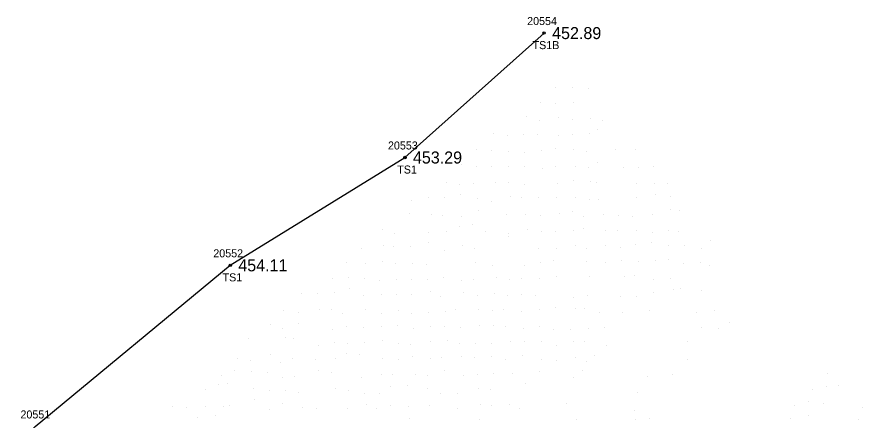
# Model space of a CAD drawing. Extents: x 1747760 to 1751131, y 649333 to 653784.
# Drawn here: x 1749099.9 to 1749205.4, y 651497.2 to 651547.5 of the extents above; entities that cross this region are included whole.
import ezdxf

# ---------------------------------------------------------------- set-up
doc = ezdxf.new("R2010")
doc.units = 0
for name, color, linetype in [('RD_DTM_BkLn2', 7, 'Continuous'), ('RD_DTM_BkLn_txCode', 7, 'Continuous'), ('RD_DTM_Spot', 7, 'Continuous'), ('RD_EX_TX_Misc_ELEV', 7, 'Continuous'), ('RD_SMD_Locator', 7, 'Continuous')]:
    doc.layers.add(name, color=color, linetype=linetype)

msp = doc.modelspace()

# ---------------------------------------------------------------- linework, layer by layer
at = {"layer": 'RD_DTM_BkLn2'}
msp.add_lwpolyline([(1749072.45, 651463.57), (1749102.17, 651496.37), (1749126.54, 651516.47), (1749148.35, 651529.92), (1749165.73, 651545.44)], dxfattribs=at)
at = {"layer": 'RD_DTM_Spot'}
for p, q in [((1749167.21, 651538.67), (1749167.21, 651538.67)), ((1749169.28, 651538.7), (1749169.28, 651538.7)), ((1749171.29, 651538.5), (1749171.29, 651538.5)), ((1749165.3, 651536.76), (1749165.3, 651536.76)), ((1749167.21, 651536.69), (1749167.21, 651536.69)), ((1749169.37, 651536.81), (1749169.37, 651536.81)), ((1749163.47, 651534.99), (1749163.47, 651534.99)), ((1749165.16, 651534.49), (1749165.16, 651534.49)), ((1749167.54, 651534.9), (1749167.54, 651534.9)), ((1749169.24, 651534.7), (1749169.24, 651534.7)), ((1749171.49, 651534.78), (1749171.49, 651534.78)), ((1749173, 651534.52), (1749173, 651534.52)), ((1749172.43, 651533.45), (1749172.43, 651533.45)), ((1749159.35, 651532.94), (1749159.35, 651532.94)), ((1749161.13, 651532.71), (1749161.13, 651532.71)), ((1749163.13, 651532.76), (1749163.13, 651532.76)), ((1749164.86, 651532.77), (1749164.86, 651532.77)), ((1749167.54, 651532.69), (1749167.54, 651532.69)), ((1749169.27, 651532.75), (1749169.27, 651532.75)), ((1749171.39, 651532.86), (1749171.39, 651532.86)), ((1749167.17, 651531.08), (1749167.17, 651531.08)), ((1749169.37, 651530.98), (1749169.37, 651530.98)), ((1749157.32, 651530.86), (1749157.32, 651530.86)), ((1749159.19, 651530.83), (1749159.19, 651530.83)), ((1749161.3, 651530.69), (1749161.3, 651530.69)), ((1749163.22, 651530.58), (1749163.22, 651530.58)), ((1749165.42, 651530.85), (1749165.42, 651530.85)), ((1749171.01, 651530.7), (1749171.01, 651530.7)), ((1749174.69, 651530.92), (1749174.69, 651530.92)), ((1749177.18, 651530.96), (1749177.18, 651530.96)), ((1749155.41, 651529.01), (1749155.41, 651529.01)), ((1749172.35, 651529.27), (1749172.35, 651529.27)), ((1749157.31, 651528.79), (1749157.31, 651528.79)), ((1749159.22, 651528.74), (1749159.22, 651528.74)), ((1749161.32, 651528.76), (1749161.32, 651528.76)), ((1749163.27, 651528.78), (1749163.27, 651528.78)), ((1749165.47, 651528.58), (1749165.47, 651528.58)), ((1749167.14, 651528.79), (1749167.14, 651528.79)), ((1749169.6, 651528.85), (1749169.6, 651528.85)), ((1749171.25, 651528.63), (1749171.25, 651528.63)), ((1749175.66, 651528.64), (1749175.66, 651528.64)), ((1749177.55, 651528.71), (1749177.55, 651528.71)), ((1749179.34, 651528.84), (1749179.34, 651528.84)), ((1749153.57, 651526.76), (1749153.57, 651526.76)), ((1749159.6, 651526.86), (1749159.6, 651526.86)), ((1749161.32, 651526.77), (1749161.32, 651526.77)), ((1749169.42, 651527.04), (1749169.42, 651527.04)), ((1749171.49, 651526.91), (1749171.49, 651526.91)), ((1749172.28, 651526.85), (1749172.28, 651526.85)), ((1749155.17, 651526.59), (1749155.17, 651526.59)), ((1749156.89, 651526.73), (1749156.89, 651526.73)), ((1749163.34, 651526.58), (1749163.34, 651526.58)), ((1749167.41, 651526.7), (1749167.41, 651526.7)), ((1749177.32, 651526.64), (1749177.32, 651526.64)), ((1749179.5, 651526.71), (1749179.5, 651526.71)), ((1749181.14, 651526.71), (1749181.14, 651526.71)), ((1749151.31, 651524.97), (1749151.31, 651524.97)), ((1749153.31, 651524.92), (1749153.31, 651524.92)), ((1749155.28, 651525.25), (1749155.28, 651525.25)), ((1749157.4, 651524.86), (1749157.4, 651524.86)), ((1749161.53, 651525), (1749161.53, 651525)), ((1749162.89, 651524.91), (1749162.89, 651524.91)), ((1749165.01, 651524.92), (1749165.01, 651524.92)), ((1749167.32, 651524.94), (1749167.32, 651524.94)), ((1749169.67, 651524.93), (1749169.67, 651524.93)), ((1749171.39, 651524.66), (1749171.39, 651524.66)), ((1749172.58, 651524.71), (1749172.58, 651524.71)), ((1749177.27, 651524.98), (1749177.27, 651524.98)), ((1749179.66, 651525.26), (1749179.66, 651525.26)), ((1749181.56, 651525), (1749181.56, 651525)), ((1749149.14, 651524.6), (1749149.14, 651524.6)), ((1749159.21, 651524.47), (1749159.21, 651524.47)), ((1749148.87, 651522.98), (1749148.87, 651522.98)), ((1749151.67, 651522.85), (1749151.67, 651522.85)), ((1749153.08, 651522.65), (1749153.08, 651522.65)), ((1749155.37, 651522.62), (1749155.37, 651522.62)), ((1749157.51, 651523.29), (1749157.51, 651523.29)), ((1749161.08, 651522.81), (1749161.08, 651522.81)), ((1749163.46, 651522.78), (1749163.46, 651522.78)), ((1749165.3, 651522.7), (1749165.3, 651522.7)), ((1749167.65, 651522.98), (1749167.65, 651522.98)), ((1749169.31, 651523.2), (1749169.31, 651523.2)), ((1749170.67, 651522.53), (1749170.67, 651522.53)), ((1749173.11, 651522.85), (1749173.11, 651522.85)), ((1749175.05, 651522.63), (1749175.05, 651522.63)), ((1749176.79, 651522.58), (1749176.79, 651522.58)), ((1749179.28, 651522.85), (1749179.28, 651522.85)), ((1749181.57, 651523.41), (1749181.57, 651523.41)), ((1749182.58, 651523.37), (1749182.58, 651523.37)), ((1749156.84, 651521.55), (1749156.84, 651521.55)), ((1749145.55, 651520.88), (1749145.55, 651520.88)), ((1749147.04, 651520.48), (1749147.04, 651520.48)), ((1749151.29, 651520.56), (1749151.29, 651520.56)), ((1749153.49, 651520.75), (1749153.49, 651520.75)), ((1749155.18, 651521.34), (1749155.18, 651521.34)), ((1749158.41, 651520.66), (1749158.41, 651520.66)), ((1749161.22, 651520.48), (1749161.22, 651520.48)), ((1749163.69, 651520.95), (1749163.69, 651520.95)), ((1749165.35, 651520.7), (1749165.35, 651520.7)), ((1749167.14, 651520.67), (1749167.14, 651520.67)), ((1749169.34, 651520.76), (1749169.34, 651520.76)), ((1749170.62, 651521.04), (1749170.62, 651521.04)), ((1749173.36, 651520.79), (1749173.36, 651520.79)), ((1749174.86, 651520.82), (1749174.86, 651520.82)), ((1749177.27, 651520.86), (1749177.27, 651520.86)), ((1749179.32, 651520.55), (1749179.32, 651520.55)), ((1749181.27, 651520.85), (1749181.27, 651520.85)), ((1749182.51, 651520.68), (1749182.51, 651520.68)), ((1749161.25, 651520.06), (1749161.25, 651520.06)), ((1749186.45, 651519.55), (1749186.45, 651519.55)), ((1749142.97, 651518.58), (1749142.97, 651518.58)), ((1749145.63, 651518.96), (1749145.63, 651518.96)), ((1749146.86, 651518.88), (1749146.86, 651518.88)), ((1749149.06, 651518.76), (1749149.06, 651518.76)), ((1749151.32, 651519.29), (1749151.32, 651519.29)), ((1749155.48, 651518.97), (1749155.48, 651518.97)), ((1749157.04, 651518.59), (1749157.04, 651518.59)), ((1749164.98, 651518.63), (1749164.98, 651518.63)), ((1749167.22, 651518.56), (1749167.22, 651518.56)), ((1749169.63, 651518.96), (1749169.63, 651518.96)), ((1749171.05, 651518.6), (1749171.05, 651518.6)), ((1749173.38, 651518.99), (1749173.38, 651518.99)), ((1749175.23, 651518.7), (1749175.23, 651518.7)), ((1749177.12, 651519.1), (1749177.12, 651519.1)), ((1749179.14, 651519.27), (1749179.14, 651519.27)), ((1749181.22, 651518.98), (1749181.22, 651518.98)), ((1749183.2, 651518.89), (1749183.2, 651518.89)), ((1749185.43, 651518.53), (1749185.43, 651518.53)), ((1749153.3, 651518.3), (1749153.3, 651518.3)), ((1749141.11, 651516.79), (1749141.11, 651516.79)), ((1749143.38, 651516.76), (1749143.38, 651516.76)), ((1749145.6, 651516.96), (1749145.6, 651516.96)), ((1749147.23, 651516.76), (1749147.23, 651516.76)), ((1749149.34, 651516.64), (1749149.34, 651516.64)), ((1749151.05, 651516.57), (1749151.05, 651516.57)), ((1749157.19, 651516.87), (1749157.19, 651516.87)), ((1749159.27, 651516.44), (1749159.27, 651516.44)), ((1749163.29, 651516.51), (1749163.29, 651516.51)), ((1749165.33, 651516.88), (1749165.33, 651516.88)), ((1749166.93, 651517.04), (1749166.93, 651517.04)), ((1749171.02, 651517), (1749171.02, 651517)), ((1749173.41, 651516.84), (1749173.41, 651516.84)), ((1749175.45, 651517.11), (1749175.45, 651517.11)), ((1749177.57, 651516.95), (1749177.57, 651516.95)), ((1749179.66, 651517.06), (1749179.66, 651517.06)), ((1749181.25, 651517.24), (1749181.25, 651517.24)), ((1749183.11, 651516.64), (1749183.11, 651516.64)), ((1749185.26, 651516.87), (1749185.26, 651516.87)), ((1749186.44, 651516.51), (1749186.44, 651516.51)), ((1749177.02, 651515.25), (1749177.02, 651515.25)), ((1749139.35, 651514.86), (1749139.35, 651514.86)), ((1749141.29, 651514.98), (1749141.29, 651514.98)), ((1749143.25, 651514.77), (1749143.25, 651514.77)), ((1749145.2, 651514.58), (1749145.2, 651514.58)), ((1749147.35, 651514.71), (1749147.35, 651514.71)), ((1749149.19, 651514.75), (1749149.19, 651514.75)), ((1749151.15, 651514.69), (1749151.15, 651514.69)), ((1749153.19, 651514.94), (1749153.19, 651514.94)), ((1749155.38, 651514.58), (1749155.38, 651514.58)), ((1749156.93, 651514.68), (1749156.93, 651514.68)), ((1749159.73, 651515), (1749159.73, 651515)), ((1749161.4, 651514.71), (1749161.4, 651514.71)), ((1749162.92, 651514.82), (1749162.92, 651514.82)), ((1749165.17, 651514.84), (1749165.17, 651514.84)), ((1749167.28, 651515.06), (1749167.28, 651515.06)), ((1749171.45, 651515.04), (1749171.45, 651515.04)), ((1749175.8, 651515.05), (1749175.8, 651515.05)), ((1749179.36, 651514.74), (1749179.36, 651514.74)), ((1749181.57, 651514.87), (1749181.57, 651514.87)), ((1749139.56, 651513.04), (1749139.56, 651513.04)), ((1749141.48, 651513.52), (1749141.48, 651513.52)), ((1749151.52, 651513.21), (1749151.52, 651513.21)), ((1749155.69, 651513.05), (1749155.69, 651513.05)), ((1749179.4, 651513.05), (1749179.4, 651513.05)), ((1749181.88, 651513.5), (1749181.88, 651513.5)), ((1749182.76, 651513.64), (1749182.76, 651513.64)), ((1749185.38, 651513.38), (1749185.38, 651513.38)), ((1749135.49, 651512.98), (1749135.49, 651512.98)), ((1749137.37, 651512.91), (1749137.37, 651512.91)), ((1749143.19, 651512.68), (1749143.19, 651512.68)), ((1749145.4, 651512.83), (1749145.4, 651512.83)), ((1749147.34, 651512.89), (1749147.34, 651512.89)), ((1749149.15, 651512.83), (1749149.15, 651512.83)), ((1749152.85, 651512.63), (1749152.85, 651512.63)), ((1749157.47, 651512.75), (1749157.47, 651512.75)), ((1749159.54, 651512.94), (1749159.54, 651512.94)), ((1749161.13, 651512.75), (1749161.13, 651512.75)), ((1749162.96, 651512.88), (1749162.96, 651512.88)), ((1749164.61, 651512.7), (1749164.61, 651512.7)), ((1749169.39, 651512.48), (1749169.39, 651512.48)), ((1749171.18, 651512.74), (1749171.18, 651512.74)), ((1749175.28, 651512.63), (1749175.28, 651512.63)), ((1749177.31, 651512.53), (1749177.31, 651512.53)), ((1749137.62, 651510.98), (1749137.62, 651510.98)), ((1749143.37, 651510.95), (1749143.37, 651510.95)), ((1749154.69, 651511.02), (1749154.69, 651511.02)), ((1749157.56, 651510.92), (1749157.56, 651510.92)), ((1749160.66, 651510.99), (1749160.66, 651510.99)), ((1749167.15, 651511.15), (1749167.15, 651511.15)), ((1749169.59, 651511.03), (1749169.59, 651511.03)), ((1749170.83, 651511.03), (1749170.83, 651511.03)), ((1749133.13, 651510.8), (1749133.13, 651510.8)), ((1749135.09, 651510.53), (1749135.09, 651510.53)), ((1749139.24, 651510.9), (1749139.24, 651510.9)), ((1749140.52, 651510.41), (1749140.52, 651510.41)), ((1749145.38, 651510.49), (1749145.38, 651510.49)), ((1749147.6, 651510.89), (1749147.6, 651510.89)), ((1749149.12, 651510.46), (1749149.12, 651510.46)), ((1749151.32, 651510.58), (1749151.32, 651510.58)), ((1749153.37, 651510.76), (1749153.37, 651510.76)), ((1749159.27, 651510.85), (1749159.27, 651510.85)), ((1749162.93, 651510.66), (1749162.93, 651510.66)), ((1749165.17, 651510.92), (1749165.17, 651510.92)), ((1749172.6, 651510.63), (1749172.6, 651510.63)), ((1749175.47, 651510.58), (1749175.47, 651510.58)), ((1749178.93, 651510.8), (1749178.93, 651510.8)), ((1749184.8, 651510.6), (1749184.8, 651510.6)), ((1749187, 651510.87), (1749187, 651510.87)), ((1749131.52, 651509.09), (1749131.52, 651509.09)), ((1749135.06, 651509.18), (1749135.06, 651509.18)), ((1749145.45, 651508.86), (1749145.45, 651508.86)), ((1749147.37, 651508.93), (1749147.37, 651508.93)), ((1749153.23, 651508.87), (1749153.23, 651508.87)), ((1749157.62, 651508.98), (1749157.62, 651508.98)), ((1749159.36, 651509), (1749159.36, 651509)), ((1749165.18, 651508.81), (1749165.18, 651508.81)), ((1749188.87, 651509.3), (1749188.87, 651509.3)), ((1749133.07, 651508.56), (1749133.07, 651508.56)), ((1749139.34, 651508.41), (1749139.34, 651508.41)), ((1749141.03, 651508.78), (1749141.03, 651508.78)), ((1749143.23, 651508.71), (1749143.23, 651508.71)), ((1749149.47, 651508.65), (1749149.47, 651508.65)), ((1749151.5, 651508.79), (1749151.5, 651508.79)), ((1749155.32, 651508.72), (1749155.32, 651508.72)), ((1749160.91, 651508.78), (1749160.91, 651508.78)), ((1749163.2, 651508.6), (1749163.2, 651508.6)), ((1749166.9, 651508.52), (1749166.9, 651508.52)), ((1749168.98, 651508.45), (1749168.98, 651508.45)), ((1749171.31, 651508.55), (1749171.31, 651508.55)), ((1749173.29, 651508.72), (1749173.29, 651508.72)), ((1749185.38, 651508.66), (1749185.38, 651508.66)), ((1749187.47, 651508.55), (1749187.47, 651508.55)), ((1749128.8, 651507.33), (1749128.8, 651507.33)), ((1749133.42, 651507.41), (1749133.42, 651507.41)), ((1749134.45, 651507.39), (1749134.45, 651507.39)), ((1749139.61, 651506.82), (1749139.61, 651506.82)), ((1749143.27, 651506.83), (1749143.27, 651506.83)), ((1749145.55, 651507.04), (1749145.55, 651507.04)), ((1749151.49, 651507.03), (1749151.49, 651507.03)), ((1749153.63, 651507.1), (1749153.63, 651507.1)), ((1749157.2, 651506.77), (1749157.2, 651506.77)), ((1749159.18, 651506.73), (1749159.18, 651506.73)), ((1749161.54, 651507.02), (1749161.54, 651507.02)), ((1749163.31, 651506.91), (1749163.31, 651506.91)), ((1749165.46, 651506.99), (1749165.46, 651506.99)), ((1749169.41, 651507.02), (1749169.41, 651507.02)), ((1749170.76, 651507.01), (1749170.76, 651507.01)), ((1749183.65, 651507), (1749183.65, 651507)), ((1749137.53, 651506.52), (1749137.53, 651506.52)), ((1749141.14, 651506.67), (1749141.14, 651506.67)), ((1749147.51, 651506.68), (1749147.51, 651506.68)), ((1749149.1, 651506.61), (1749149.1, 651506.61)), ((1749155.13, 651506.66), (1749155.13, 651506.66)), ((1749167.33, 651506.47), (1749167.33, 651506.47)), ((1749173.47, 651506.44), (1749173.47, 651506.44)), ((1749127.48, 651504.91), (1749127.48, 651504.91)), ((1749129.01, 651504.59), (1749129.01, 651504.59)), ((1749131.6, 651505.36), (1749131.6, 651505.36)), ((1749134.26, 651504.84), (1749134.26, 651504.84)), ((1749137.21, 651504.78), (1749137.21, 651504.78)), ((1749139.71, 651504.8), (1749139.71, 651504.8)), ((1749141.06, 651505.49), (1749141.06, 651505.49)), ((1749142.67, 651505.36), (1749142.67, 651505.36)), ((1749145.5, 651504.86), (1749145.5, 651504.86)), ((1749147.54, 651504.68), (1749147.54, 651504.68)), ((1749149.35, 651505.14), (1749149.35, 651505.14)), ((1749151.5, 651504.87), (1749151.5, 651504.87)), ((1749152.87, 651504.96), (1749152.87, 651504.96)), ((1749155.41, 651505.05), (1749155.41, 651505.05)), ((1749157.04, 651504.96), (1749157.04, 651504.96)), ((1749159.11, 651505.08), (1749159.11, 651505.08)), ((1749160.94, 651504.78), (1749160.94, 651504.78)), ((1749163.01, 651505.22), (1749163.01, 651505.22)), ((1749165.38, 651504.72), (1749165.38, 651504.72)), ((1749167.3, 651504.66), (1749167.3, 651504.66)), ((1749169.69, 651504.97), (1749169.69, 651504.97)), ((1749172.01, 651505.25), (1749172.01, 651505.25)), ((1749183.58, 651504.71), (1749183.58, 651504.71)), ((1749132.76, 651504.34), (1749132.76, 651504.34)), ((1749170.96, 651504.43), (1749170.96, 651504.43)), ((1749125.41, 651502.76), (1749125.41, 651502.76)), ((1749127.08, 651503.4), (1749127.08, 651503.4)), ((1749129.18, 651503.25), (1749129.18, 651503.25)), ((1749131.13, 651503.05), (1749131.13, 651503.05)), ((1749134.54, 651502.65), (1749134.54, 651502.65)), ((1749137.55, 651503.36), (1749137.55, 651503.36)), ((1749139.18, 651503.1), (1749139.18, 651503.1)), ((1749142.97, 651502.49), (1749142.97, 651502.49)), ((1749145.46, 651502.81), (1749145.46, 651502.81)), ((1749146.83, 651502.89), (1749146.83, 651502.89)), ((1749149.68, 651502.85), (1749149.68, 651502.85)), ((1749151.15, 651502.73), (1749151.15, 651502.73)), ((1749153.34, 651503.36), (1749153.34, 651503.36)), ((1749155.64, 651502.75), (1749155.64, 651502.75)), ((1749157.39, 651502.84), (1749157.39, 651502.84)), ((1749159.42, 651502.98), (1749159.42, 651502.98)), ((1749161.78, 651502.97), (1749161.78, 651502.97)), ((1749165.17, 651503.2), (1749165.17, 651503.2)), ((1749169.35, 651502.47), (1749169.35, 651502.47)), ((1749170.5, 651503.41), (1749170.5, 651503.41)), ((1749178.65, 651502.66), (1749178.65, 651502.66)), ((1749181.71, 651502.91), (1749181.71, 651502.91)), ((1749201.11, 651502.95), (1749201.11, 651502.95)), ((1749125.01, 651501.59), (1749125.01, 651501.59)), ((1749126.24, 651501.73), (1749126.24, 651501.73)), ((1749133.04, 651502.43), (1749133.04, 651502.43)), ((1749148.72, 651501.5), (1749148.72, 651501.5)), ((1749163.41, 651501.76), (1749163.41, 651501.76)), ((1749202.47, 651501.5), (1749202.47, 651501.5)), ((1749123.44, 651501), (1749123.44, 651501)), ((1749129.44, 651501.06), (1749129.44, 651501.06)), ((1749131.45, 651500.91), (1749131.45, 651500.91)), ((1749133.44, 651500.83), (1749133.44, 651500.83)), ((1749135.1, 651500.57), (1749135.1, 651500.57)), ((1749139.72, 651501.11), (1749139.72, 651501.11)), ((1749141.33, 651500.86), (1749141.33, 651500.86)), ((1749143.34, 651500.45), (1749143.34, 651500.45)), ((1749145.14, 651500.54), (1749145.14, 651500.54)), ((1749146.55, 651501.37), (1749146.55, 651501.37)), ((1749151.12, 651501.16), (1749151.12, 651501.16)), ((1749152.8, 651500.53), (1749152.8, 651500.53)), ((1749154.88, 651500.45), (1749154.88, 651500.45)), ((1749157.56, 651501.12), (1749157.56, 651501.12)), ((1749159.09, 651501.03), (1749159.09, 651501.03)), ((1749177.35, 651500.6), (1749177.35, 651500.6)), ((1749199.27, 651501.02), (1749199.27, 651501.02)), ((1749200.96, 651501.32), (1749200.96, 651501.32)), ((1749129.61, 651499.74), (1749129.61, 651499.74)), ((1749198.74, 651499.54), (1749198.74, 651499.54)), ((1749119.37, 651498.87), (1749119.37, 651498.87)), ((1749121.13, 651498.68), (1749121.13, 651498.68)), ((1749123.4, 651498.86), (1749123.4, 651498.86)), ((1749125.75, 651498.91), (1749125.75, 651498.91)), ((1749126.44, 651498.96), (1749126.44, 651498.96)), ((1749131.45, 651498.48), (1749131.45, 651498.48)), ((1749133.05, 651499.27), (1749133.05, 651499.27)), ((1749135.55, 651498.78), (1749135.55, 651498.78)), ((1749137.27, 651498.6), (1749137.27, 651498.6)), ((1749141.13, 651498.6), (1749141.13, 651498.6)), ((1749143.56, 651499.13), (1749143.56, 651499.13)), ((1749144.79, 651498.6), (1749144.79, 651498.6)), ((1749146.59, 651498.94), (1749146.59, 651498.94)), ((1749148.85, 651498.89), (1749148.85, 651498.89)), ((1749151.47, 651498.93), (1749151.47, 651498.93)), ((1749154.93, 651498.57), (1749154.93, 651498.57)), ((1749157.73, 651499.08), (1749157.73, 651499.08)), ((1749159.1, 651499.02), (1749159.1, 651499.02)), ((1749161.36, 651499.07), (1749161.36, 651499.07)), ((1749162.71, 651498.59), (1749162.71, 651498.59)), ((1749168.52, 651499.2), (1749168.52, 651499.2)), ((1749176.98, 651498.37), (1749176.98, 651498.37)), ((1749196.97, 651498.93), (1749196.97, 651498.93)), ((1749200.66, 651499.21), (1749200.66, 651499.21)), ((1749205.44, 651498.76), (1749205.44, 651498.76)), ((1749122.43, 651497.5), (1749122.43, 651497.5)), ((1749124.68, 651497.73), (1749124.68, 651497.73)), ((1749148.94, 651497.34), (1749148.94, 651497.34)), ((1749169.8, 651497.28), (1749169.8, 651497.28)), ((1749177.18, 651497.2), (1749177.18, 651497.2)), ((1749178.89, 651497.41), (1749178.89, 651497.41)), ((1749196.51, 651497.31), (1749196.51, 651497.31)), ((1749198.74, 651497.78), (1749198.74, 651497.78)), ((1749204.95, 651497.3), (1749204.95, 651497.3)), ((1749157.64, 651497.19), (1749157.64, 651497.19))]:
    msp.add_line(p, q, dxfattribs=at)
at = {"layer": 'RD_SMD_Locator'}
for centre in [(1749165.73, 651545.44), (1749148.35, 651529.92), (1749126.54, 651516.47)]:
    msp.add_circle(centre, 0.15, dxfattribs=at)

# ---------------------------------------------------------------- texts
at = {"layer": 'RD_DTM_BkLn_txCode'}
for s, p in [('20554', (1749163.61, 651546.44)), ('TS1B', (1749164.29, 651543.44)), ('20553', (1749146.23, 651530.92)), ('TS1', (1749147.39, 651527.92)), ('20552', (1749124.42, 651517.47)), ('TS1', (1749125.58, 651514.47)), ('20551', (1749100.34, 651497.37))]:
    msp.add_text(s, height=1, dxfattribs=at).set_placement(p)
at = {"layer": 'RD_EX_TX_Misc_ELEV'}
for s, p in [('452.89', (1749166.73, 651544.69)), ('453.29', (1749149.35, 651529.17)), ('454.11', (1749127.54, 651515.72))]:
    msp.add_text(s, height=1.5, dxfattribs=at).set_placement(p)

doc.saveas('drawing.dxf')
